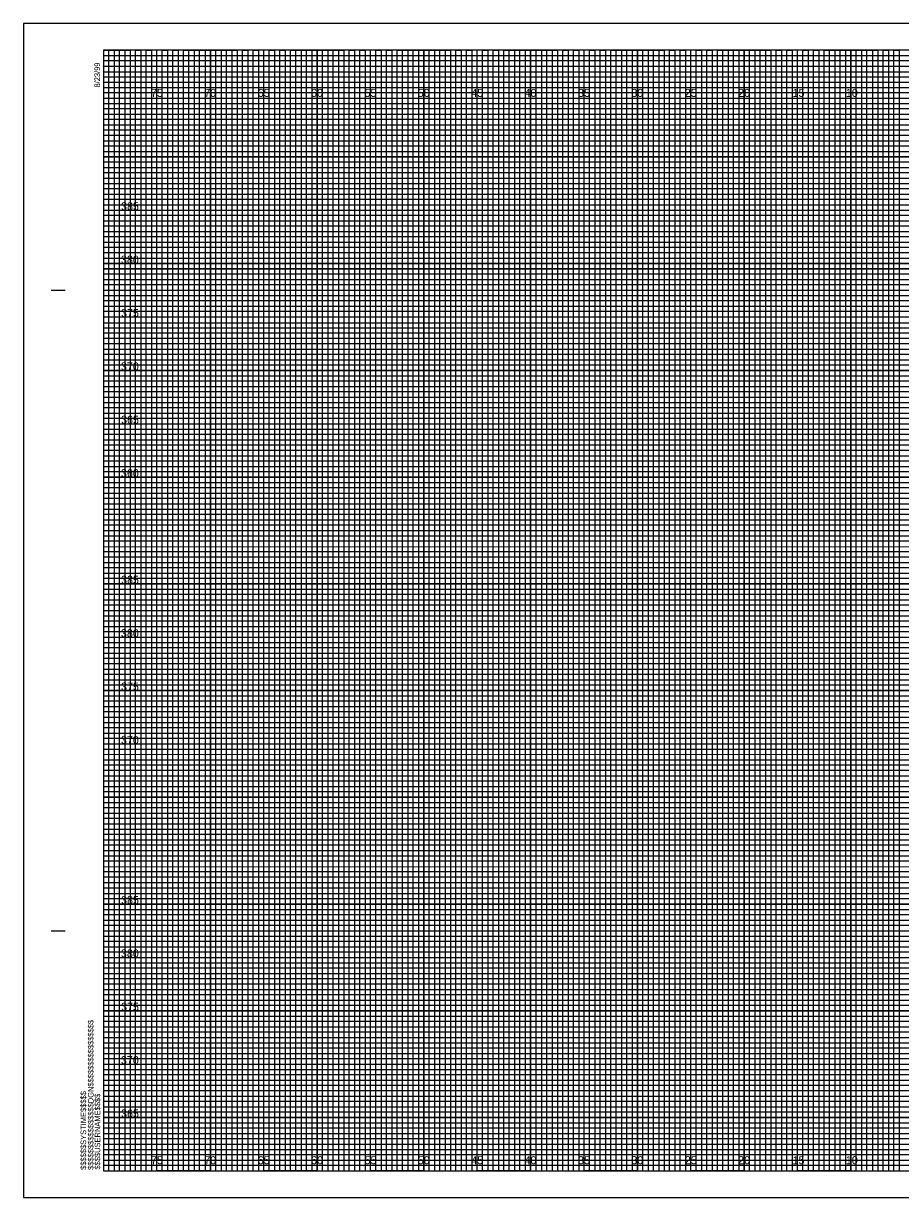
# Model space of a CAD drawing. Extents: x -8 to 162, y 218 to 328.
# Drawn here: x -7.5 to 74.6, y 217.5 to 327.5 of the extents above; entities that cross this region are included whole.
import ezdxf

# ---------------------------------------------------------------- set-up
doc = ezdxf.new("R2010")
doc.units = 0
for name, color, linetype in [('Exist XS Center Line Elevation Label', 7, 'Continuous'), ('Exist XS Ground Line', 7, 'Continuous'), ('Prop CMT Pvmt Surface', 7, 'Continuous'), ('Prop CMT Subgrade Earthwork', 7, 'Continuous'), ('Prop XS Berm Ditch', 7, 'Continuous'), ('Scratch_Level_0', 7, 'Continuous'), ('Scratch_Level_1', 7, 'Continuous'), ('Scratch_Level_2', 7, 'Continuous'), ('Typical Curb CELL', 7, 'Continuous')]:
    doc.layers.add(name, color=color, linetype=linetype)

msp = doc.modelspace()

# ---------------------------------------------------------------- linework, layer by layer
at = {"layer": 'Exist XS Center Line Elevation Label'}
for points in [[(0, 325), (2.5, 325), (2.5, 220), (7.5, 220), (7.5, 325), (12.5, 325), (12.5, 220), (17.5, 220), (17.5, 325), (22.5, 325), (22.5, 220), (27.5, 220), (27.5, 325), (32.5, 325), (32.5, 220), (37.5, 220), (37.5, 325), (42.5, 325), (42.5, 220), (47.5, 220), (47.5, 325), (52.5, 325), (52.5, 220), (57.5, 220), (57.5, 325), (62.5, 325), (62.5, 220), (67.5, 220), (67.5, 325), (72.5, 325), (72.5, 220), (77.5, 220)], [(0, 322.5), (137.5, 322.5)], [(0, 312.5), (160, 312.5), (160, 317.5), (0, 317.5)], [(0, 302.5), (160, 302.5), (160, 307.5), (0, 307.5)], [(0, 292.5), (160, 292.5), (160, 297.5), (0, 297.5)], [(0, 282.5), (160, 282.5), (160, 287.5), (0, 287.5)], [(0, 272.5), (160, 272.5), (160, 277.5), (0, 277.5)], [(0, 262.5), (160, 262.5), (160, 267.5), (0, 267.5)], [(0, 252.5), (160, 252.5), (160, 257.5), (0, 257.5)], [(0, 242.5), (160, 242.5), (160, 247.5), (0, 247.5)], [(0, 232.5), (160, 232.5), (160, 237.5), (0, 237.5)], [(0, 222.5), (160, 222.5), (160, 227.5), (0, 227.5)]]:
    msp.add_lwpolyline(points, dxfattribs=at)
at = {"layer": 'Exist XS Ground Line'}
for p, q in [((5, 325), (0, 325)), ((5, 220), (5, 325)), ((15, 325), (10, 325)), ((10, 325), (10, 220)), ((15, 220), (15, 325)), ((25, 325), (20, 325)), ((20, 325), (20, 220)), ((25, 220), (25, 325)), ((35, 325), (30, 325)), ((30, 325), (30, 220)), ((35, 220), (35, 325)), ((45, 325), (40, 325)), ((40, 325), (40, 220)), ((45, 220), (45, 325)), ((55, 325), (50, 325)), ((50, 325), (50, 220)), ((55, 220), (55, 325)), ((65, 325), (60, 325)), ((60, 325), (60, 220)), ((65, 220), (65, 325)), ((75, 325), (70, 325)), ((70, 325), (70, 220)), ((10, 220), (5, 220)), ((20, 220), (15, 220)), ((30, 220), (25, 220)), ((40, 220), (35, 220)), ((50, 220), (45, 220)), ((60, 220), (55, 220)), ((70, 220), (65, 220))]:
    msp.add_line(p, q, dxfattribs=at)
for points in [[(0, 320), (160, 320), (160, 315), (0, 315)], [(0, 310), (160, 310), (160, 305), (0, 305)], [(0, 300), (160, 300), (160, 295), (0, 295)], [(0, 290), (160, 290), (160, 285), (0, 285)], [(0, 280), (160, 280), (160, 275), (0, 275)], [(0, 270), (160, 270), (160, 265), (0, 265)], [(0, 260), (160, 260), (160, 255), (0, 255)], [(0, 250), (160, 250), (160, 245), (0, 245)], [(0, 240), (160, 240), (160, 235), (0, 235)], [(0, 230), (160, 230), (160, 225), (0, 225)]]:
    msp.add_lwpolyline(points, dxfattribs=at)
at = {"layer": 'Prop CMT Subgrade Earthwork'}
msp.add_lwpolyline([(-7.5, 217.5), (162.5, 217.5), (162.5, 327.5), (-7.5, 327.5)], close=True, dxfattribs=at)
at = {"layer": 'Prop XS Berm Ditch'}
for p, q in [((0, 324.5), (130, 324.5)), ((130, 323.99), (0, 323.99)), ((0, 323.99), (0, 323.5)), ((0, 323.5), (130, 323.5)), ((130, 322.94), (0, 322.94)), ((0, 322.94), (0, 322)), ((0, 322), (160, 322))]:
    msp.add_line(p, q, dxfattribs=at)
for points in [[(0, 321.5), (135, 321.5), (160, 321.5), (160, 321), (0, 321)], [(0, 320.5), (160, 320.5), (160, 319.5), (0, 319.5)], [(0, 319), (160, 319), (160, 318.5), (0, 318.49)], [(0, 318), (160, 318), (160, 317), (0, 317)], [(0, 316.5), (160, 316.5), (160, 316), (0, 316)], [(0, 315.5), (160, 315.5), (160, 314.5), (0, 314.5)], [(0, 314), (160, 314), (160, 313.5), (0, 313.5)], [(0, 313), (160, 313), (160, 312), (0, 312)], [(0, 311.5), (160, 311.5), (160, 311), (0, 311)], [(0, 310.5), (160, 310.5), (160, 309.5), (0, 309.5)], [(0, 309), (160, 309), (160, 308.5), (0, 308.5)], [(0, 308), (160, 308), (160, 306.98), (160, 306.5), (160, 306), (0, 306)], [(0, 307), (160, 307), (160, 306.5), (0, 306.5)], [(0, 305.5), (160, 305.5), (160, 304.5), (0, 304.51)], [(0, 304.51), (160, 304.5), (160, 304), (0, 304)], [(0, 303.5), (160, 303.5), (160, 303), (0, 303)], [(0, 302), (160, 302), (160, 301.5), (0, 301.5)], [(0, 301), (160, 301), (160, 300.5), (0, 300.5)], [(-0.04, 299.44), (160, 299.44), (160, 298.94), (-0.04, 298.94)], [(0, 298.5), (160, 298.5), (160, 298), (0, 298)], [(0, 297), (160, 297), (160, 296.5), (0, 296.5)], [(0, 296), (160, 296), (160, 295.5), (0, 295.5)], [(0, 294.5), (160, 294.5), (160, 294), (0, 294)], [(0, 293.5), (160, 293.5), (160, 293), (0, 293)], [(0, 292), (160, 292), (160, 291.5), (0, 291.5)], [(0, 291), (160, 291), (160, 290.5), (0, 290.5)], [(0, 289.5), (160, 289.5), (160, 288.99), (0, 289)], [(0, 288.5), (160, 288.5), (160, 288), (0, 288)], [(0, 287), (160, 287), (160, 286.5), (0, 286.5)], [(0, 286), (160, 286), (160, 285.5), (0, 285.5)], [(0, 284.5), (160, 284.5), (160, 284), (0, 284)], [(0, 283.5), (160, 283.5), (160, 283), (0, 283)], [(0, 282), (160, 282), (160, 281.5), (0, 281.5)], [(0, 281), (160, 281), (160, 280.5), (0, 280.5)], [(0, 279.5), (160, 279.5), (160, 279), (0, 279)], [(0, 278.5), (160.03, 278.45), (160, 278), (0, 278)], [(0, 277), (160, 277), (160, 276.5), (0, 276.5)], [(0, 276), (160, 276), (160, 275.5), (0, 275.5)], [(0, 274.5), (160, 274.5), (160, 274), (0, 274)], [(0, 273.5), (160, 273.5), (160, 273), (0, 273)], [(0, 272), (160, 272), (160, 271.5), (0, 271.5)], [(0, 271), (160, 271), (160, 270.5), (0, 270.5)], [(0, 269.5), (160, 269.5), (160, 269), (0, 269)], [(0, 268.5), (160, 268.5), (160, 268), (0, 268)], [(0, 267), (160, 267), (160, 266.5), (0, 266.5)], [(0, 266), (160, 266), (160, 265.5), (0, 265.5)], [(0, 264.5), (160, 264.5), (160, 264), (0, 264)], [(0, 263.5), (160, 263.5), (160, 263), (0, 263)], [(0, 262), (160, 262), (160, 261.5), (0, 261.5)], [(0, 261), (160, 261), (160, 260.5), (0, 260.5)], [(0, 259.5), (160, 259.5), (160, 258.99), (0, 259)], [(0, 258.5), (160, 258.5), (160, 258), (0, 258)], [(0, 257), (160, 257), (160, 256.5), (0, 256.5)], [(0, 256), (160, 256), (160, 255.5), (0, 255.5)], [(0, 254.5), (160, 254.5), (160, 254), (0, 254)], [(0, 253.5), (160, 253.5), (160, 253), (0, 253)], [(0, 252), (160, 252), (160, 251.5), (0, 251.5)], [(0, 251), (160, 251), (160, 250.5), (0, 250.5)], [(0, 249.5), (160, 249.5), (160, 249), (0, 249)], [(0, 248.5), (160.03, 248.46), (160, 248), (0, 248)], [(0, 247), (160, 247), (160, 246.5), (0, 246.5)], [(0, 246), (160, 246), (160, 245.5), (0, 245.5)], [(0, 244.5), (160, 244.5), (160, 244), (0, 244)], [(0, 243.5), (160, 243.5), (160, 243), (0, 243)], [(0, 242), (160, 242), (160, 241.5), (0, 241.5)], [(0, 241), (160, 241), (160, 240.5), (0, 240.5)], [(0, 239.5), (160, 239.5), (160, 239), (0, 239)], [(0, 238.5), (160, 238.5), (160, 238), (0, 238)], [(0, 237), (160, 237), (160, 236.5), (0, 236.5)], [(0, 236), (160, 236), (160, 235.5), (0, 235.5)], [(0, 234.5), (160, 234.5), (160, 234), (0, 234)], [(0, 233.5), (160, 233.5), (160, 233), (0, 233)], [(0, 232), (160, 232), (160, 231.5), (0, 231.5)], [(0, 231), (160, 231), (160, 230.5), (0, 230.5)], [(0, 229.5), (160, 229.5), (160, 229), (0, 229)], [(0, 228.5), (160, 228.5), (160, 228), (0, 228)], [(0, 227), (160, 227), (160, 226.5), (0, 226.5)], [(0, 226), (160, 226), (160, 225.5), (0, 225.5)], [(0, 224.5), (160, 224.5), (160, 224), (0, 224)], [(0, 223.5), (160, 223.5), (160, 223), (0, 223)], [(0, 222), (160, 222), (160, 221.5), (0, 221.5)], [(0, 221), (160, 221), (160, 220.5), (0, 220.5)]]:
    msp.add_lwpolyline(points, dxfattribs=at)
at = {"layer": 'Scratch_Level_1'}
for points in [[(0, 220), (0.5, 220), (0.5, 325), (1, 325), (1, 220)], [(1, 220), (1.5, 220), (1.5, 325), (2, 325), (2, 220)], [(2.5, 220), (3, 220), (3, 325), (3.5, 325), (3.5, 220)], [(3.5, 220), (4, 220), (4, 325), (4.5, 325), (4.5, 220)], [(5, 220), (5.5, 220), (5.5, 325), (6, 325), (6, 220)], [(6, 220), (6.5, 220), (6.5, 325), (7, 325), (7, 220)], [(7.5, 220), (8, 220), (8, 325), (8.5, 325), (8.5, 220)], [(8.5, 220), (9, 220), (9, 325), (9.5, 325), (9.5, 220)], [(10, 220), (10.5, 220), (10.5, 325), (11, 325), (11, 220)], [(11, 220), (11.5, 220), (11.5, 325), (12, 325), (12, 220)], [(12.5, 220), (13, 220), (13, 325), (13.5, 325), (13.5, 220)], [(13.5, 220), (14, 220), (14, 325), (14.5, 325), (14.5, 220)], [(15, 220), (15.5, 220), (15.5, 325), (16, 325), (16, 220)], [(16, 220), (16.5, 220), (16.5, 325), (17, 325), (17, 220)], [(17.5, 220), (18, 220), (18, 325), (18.5, 325), (18.5, 220)], [(18.5, 220), (19, 220), (19, 325), (19.5, 325), (19.5, 220)], [(20, 220), (20.5, 220), (20.5, 325), (21, 325), (21, 220)], [(21, 220), (21.5, 220), (21.5, 325), (22, 325), (22, 220)], [(22.5, 220), (23, 220), (23, 325), (23.5, 325), (23.5, 220)], [(23.5, 220), (24, 220), (24, 325), (24.5, 325), (24.5, 220)], [(25, 220), (25.5, 220), (25.5, 325), (26, 325), (26, 220)], [(26, 220), (26.5, 220), (26.5, 325), (27, 325), (27, 220)], [(27.5, 220), (28, 220), (28, 325), (28.5, 325), (28.5, 220)], [(28.5, 220), (29, 220), (29, 325), (29.5, 325), (29.5, 220)], [(30, 220), (30.5, 220), (30.5, 325), (31, 325), (31, 220)], [(31, 220), (31.5, 220), (31.5, 325), (32, 325), (32, 220)], [(32.5, 220), (33, 220), (33, 325), (33.5, 325), (33.5, 220)], [(33.5, 220), (34, 220), (34, 325), (34.5, 325), (34.5, 220)], [(35, 220), (35.5, 220), (35.5, 325), (36, 325), (36, 220)], [(36, 220), (36.5, 220), (36.5, 325), (37, 325), (37, 220)], [(37.5, 220), (38, 220), (38, 325), (38.5, 325), (38.5, 220)], [(38.5, 220), (39, 220), (39, 325), (39.5, 325), (39.5, 220)], [(40, 220), (40.5, 220), (40.5, 325), (41, 325), (41, 220)], [(41, 220), (41.5, 220), (41.5, 325), (42, 325), (42, 220)], [(42.5, 220), (43, 220), (43, 325), (43.5, 325), (43.5, 220)], [(43.5, 220), (44, 220), (44, 325), (44.5, 325), (44.5, 220)], [(45, 220), (45.5, 220), (45.5, 325), (46, 325), (46, 220)], [(46, 220), (46.5, 220), (46.5, 325), (47, 325), (47, 220)], [(47.5, 220), (48, 220), (48, 325), (48.5, 325), (48.5, 220)], [(48.5, 220), (49, 220), (49, 325), (49.5, 325), (49.5, 220)], [(50, 220), (50.5, 220), (50.5, 325), (51, 325), (51, 220)], [(51, 220), (51.5, 220), (51.5, 325), (52, 325), (52, 220)], [(52.5, 220), (53, 220), (53, 325), (53.5, 325), (53.5, 220)], [(53.5, 220), (54, 220), (54, 325), (54.5, 325), (54.5, 220)], [(55, 220), (55.5, 220), (55.5, 325), (56, 325), (56, 220)], [(56, 220), (56.5, 220), (56.5, 325), (57, 325), (57, 220)], [(57.5, 220), (58, 220), (58, 325), (58.5, 325), (58.5, 220)], [(58.5, 220), (59, 220), (59, 325), (59.5, 325), (59.5, 220)], [(60, 220), (60.5, 220), (60.5, 325), (61, 325), (61, 220)], [(61, 220), (61.5, 220), (61.5, 325), (62, 325), (62, 220)], [(62.5, 220), (63, 220), (63, 325), (63.5, 325), (63.5, 220)], [(63.5, 220), (64, 220), (64, 325), (64.5, 325), (64.5, 220)], [(65, 220), (65.5, 220), (65.5, 325), (66, 325), (66, 220)], [(66, 220), (66.5, 220), (66.5, 325), (67, 325), (67, 220)], [(67.5, 220), (68, 220), (68, 325), (68.5, 325), (68.5, 220)], [(68.5, 220), (69, 220), (69, 325), (69.5, 325), (69.5, 220)], [(70, 220), (70.5, 220), (70.5, 325), (71, 325), (71, 220)], [(71, 220), (71.5, 220), (71.5, 325), (72, 325), (72, 220)], [(72.5, 220), (73, 220), (73, 325), (73.5, 325), (73.5, 220)], [(73.5, 220), (74, 220), (74, 325), (74.5, 325), (74.5, 220)]]:
    msp.add_lwpolyline(points, dxfattribs=at)
at = {"layer": 'Scratch_Level_2'}
for p, q in [((5, 220), (5, 325)), ((10, 220), (10, 325)), ((15, 220), (15, 325)), ((20, 220), (20, 325)), ((25, 220), (25, 325)), ((30, 220), (30, 325)), ((35, 220), (35, 325)), ((40, 220), (40, 325)), ((45, 220), (45, 325)), ((50, 220), (50, 325)), ((55, 220), (55, 325)), ((60, 220), (60, 325)), ((65, 220), (65, 325)), ((70, 220), (70, 325)), ((0, 320), (160, 320)), ((0, 315), (160, 315)), ((0, 310), (160, 310)), ((0, 305), (160, 305)), ((0, 300), (160, 300)), ((0, 295), (160, 295)), ((0, 290), (160, 290)), ((0, 285), (160, 285)), ((0, 280), (160, 280)), ((0, 275), (160, 275)), ((0, 270), (160, 270)), ((0, 265), (160, 265)), ((0, 260), (160, 260)), ((0, 255), (160, 255)), ((0, 250), (160, 250)), ((0, 245), (160, 245)), ((0, 240), (160, 240)), ((0, 235), (160, 235)), ((0, 230), (160, 230)), ((0, 225), (160, 225))]:
    msp.add_line(p, q, dxfattribs=at)
at = {"layer": 'Typical Curb CELL'}
for p, q in [((-4.9, 302.5), (-3.65, 302.5)), ((-4.85, 302.5), (-3.6, 302.5)), ((-4.9, 242.5), (-3.65, 242.5)), ((-4.85, 242.5), (-3.6, 242.5)), ((0, 220), (0, 220)), ((0, 220), (0, 220)), ((0, 220), (0, 220)), ((0, 220), (0, 220)), ((0, 220), (0, 220)), ((0, 220), (0, 220)), ((0, 220), (0, 220))]:
    msp.add_line(p, q, dxfattribs=at)
msp.add_lwpolyline([(160, 325), (0, 325), (0, 220), (160, 220)], close=True, dxfattribs=at)

# ---------------------------------------------------------------- texts
at = {"layer": 'Prop CMT Pvmt Surface'}
for s, p in [('385', (1.64, 310)), ('380', (1.63, 305)), ('375', (1.64, 300)), ('370', (1.63, 295)), ('365', (1.64, 290)), ('360', (1.63, 285)), ('385', (1.64, 275)), ('380', (1.63, 270)), ('375', (1.64, 265)), ('370', (1.63, 260)), ('385', (1.64, 245)), ('380', (1.63, 240)), ('375', (1.64, 235)), ('370', (1.63, 230)), ('365', (1.64, 225))]:
    msp.add_text(s, height=0.75, dxfattribs=at).set_placement(p)
at = {"layer": 'Scratch_Level_0'}
for s, p in [('75', (4.44, 320.62)), ('70', (9.43, 320.62)), ('65', (14.44, 320.62)), ('60', (19.43, 320.62)), ('55', (24.44, 320.62)), ('50', (29.43, 320.62)), ('45', (34.44, 320.62)), ('40', (39.43, 320.62)), ('35', (44.44, 320.62)), ('30', (49.43, 320.62)), ('25', (54.44, 320.62)), ('20', (59.43, 320.62)), ('15', (64.53, 320.62)), ('10', (69.52, 320.62)), ('75', (4.44, 220.62)), ('70', (9.43, 220.62)), ('65', (14.44, 220.62)), ('60', (19.43, 220.62)), ('55', (24.44, 220.62)), ('50', (29.43, 220.62)), ('45', (34.44, 220.62)), ('40', (39.43, 220.62)), ('35', (44.44, 220.62)), ('30', (49.43, 220.62)), ('25', (54.44, 220.62)), ('20', (59.43, 220.62)), ('15', (64.53, 220.62)), ('10', (69.52, 220.62))]:
    msp.add_text(s, height=0.75, dxfattribs=at).set_placement(p)
at = {"layer": 'Typical Curb CELL'}
for s, p in [('8/23/99', (-0.33, 321.5)), ('$$$$$$$$$$$$$$$$DGN$$$$$$$$$$$$$$$$', (-0.94, 220.09)), ('$$$$$$SYSTIME$$$$$', (-1.63, 220.09)), ('$$$$USERNAME$$$$', (-0.31, 220.12))]:
    msp.add_text(s, height=0.525, rotation=90, dxfattribs=at).set_placement(p)

doc.saveas('drawing.dxf')
